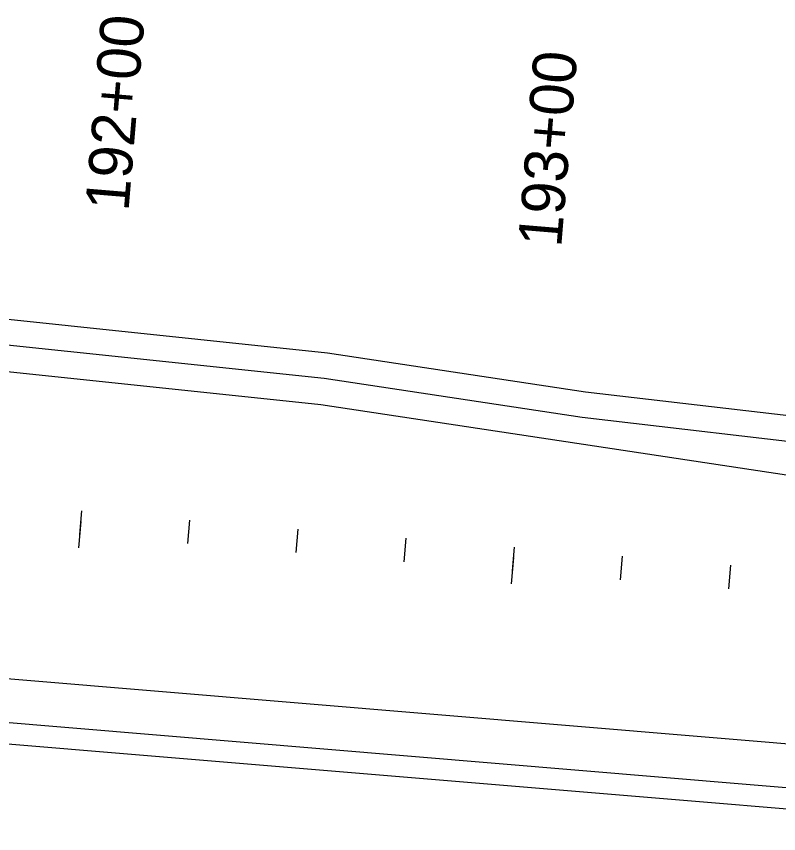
# Model space of a CAD drawing. Extents: x 20499216 to 20505321, y 7953487 to 7960535.
# Drawn here: x 20502889.6 to 20503065.2, y 7953725.8 to 7953914.1 of the extents above; entities that cross this region are included whole.
import ezdxf

# ---------------------------------------------------------------- set-up
doc = ezdxf.new("R2010")
doc.units = 0
for name, color, linetype in [('EXT_CU', 7, 'Continuous'), ('EXT_RR', 7, 'Continuous'), ('NamedBoundary', 7, 'Continuous'), ('Safety', 7, 'Continuous')]:
    doc.layers.add(name, color=color, linetype=linetype)

msp = doc.modelspace()

# ---------------------------------------------------------------- linework, layer by layer
at = {"layer": 'EXT_CU'}
for points in [[(20502662.5, 7953868.05), (20502961.27, 7953836.6), (20503020.68, 7953827.63), (20503141.39, 7953813.56), (20503176.54, 7953810.63), (20503176.04, 7953804.65), (20503140.79, 7953807.58), (20503019.89, 7953821.68), (20502960.51, 7953830.65), (20502661.92, 7953862.08), (20502601.24, 7953867.37), (20502601.76, 7953873.35)], [(20502648, 7953789.06), (20502707.64, 7953779.82), (20502721.7, 7953772.58), (20502825.48, 7953756.63), (20503134.77, 7953730.82), (20503134.36, 7953725.84), (20503134.36, 7953725.84), (20502824.89, 7953751.67), (20502720.14, 7953767.76), (20502706.07, 7953775), (20502647.4, 7953784.09), (20502614.01, 7953786.99), (20502598.64, 7953783.31), (20502593.96, 7953783.72), (20502594.39, 7953788.7), (20502598.26, 7953788.36), (20502613.64, 7953792.05)]]:
    msp.add_lwpolyline(points, close=True, dxfattribs=at)
at = {"layer": 'EXT_RR'}
for p, q in [((20502904.44, 7953797.77), (20502903.93, 7953791.67)), ((20502929.1, 7953792.64), (20502929.55, 7953798.08)), ((20502954.01, 7953790.56), (20502954.47, 7953796)), ((20502978.92, 7953788.48), (20502979.38, 7953793.92)), ((20503004.09, 7953789.45), (20503003.58, 7953783.36)), ((20503028.75, 7953784.33), (20503029.21, 7953789.77)), ((20503053.66, 7953782.25), (20503054.12, 7953787.69))]:
    msp.add_line(p, q, dxfattribs=at)
at = {"layer": 'NamedBoundary'}
for points in [[(20502611.92, 7953860.41), (20502661.35, 7953856.11), (20502959.75, 7953824.69), (20503138.13, 7953797.77), (20503167.85, 7953795.29), (20503167.85, 7953795.29)], [(20503175.04, 7953737.5), (20502826.66, 7953766.57), (20502648.32, 7953794.05), (20502594.72, 7953798.71), (20502594.72, 7953798.71)]]:
    msp.add_lwpolyline(points, dxfattribs=at)
at = {"layer": 'Safety'}
for p, q in [((20502904.18, 7953794.72), (20502904.64, 7953800.16)), ((20503003.84, 7953786.4), (20503004.29, 7953791.85))]:
    msp.add_line(p, q, dxfattribs=at)

# ---------------------------------------------------------------- texts
at = {"layer": 'EXT_RR'}
for s, p in [('192+00', (20502915.41, 7953869.04)), ('193+00', (20503015.07, 7953860.73))]:
    msp.add_text(s, height=10.02, rotation=85.2296, dxfattribs=at).set_placement(p)

doc.saveas('drawing.dxf')
